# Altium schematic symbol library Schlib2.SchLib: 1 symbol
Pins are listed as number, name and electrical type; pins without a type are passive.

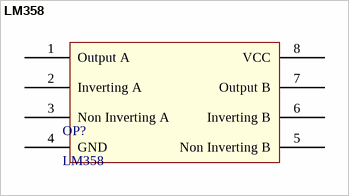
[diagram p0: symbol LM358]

## LM358
designator OP?
footprint LM358
footprint LM358
pins: 1 Output A, 2 Inverting A, 3 Non Inverting A, 4 GND, 5 Non Inverting B, 6 Inverting B, 7 Output B, 8 VCC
